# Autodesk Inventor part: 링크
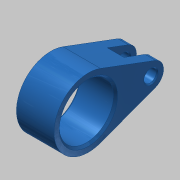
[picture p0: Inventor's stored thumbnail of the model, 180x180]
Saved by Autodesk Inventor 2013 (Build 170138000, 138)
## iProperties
Created: 2016-08
Part Number: 링크
Material: 강철, 탄소
Document SubType Name: Modeling
Designer: mduedu
Density: 7.87 g/cm^3
Mass: 80.4018 g
Surface Area: 54.1946 cm^2
Volume: 10.2162 cm^3
Author: mduedu
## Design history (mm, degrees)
sketch "스케치1"
  geometry: L1 (32.1, 5.62)-(5.775, 15.456); L2 (32.1, -5.62)-(5.775, -15.456); C1 r 13 at (0, 0); C2 r 3 at (30, 0); A1 r 16.5 centre (0, 0) between (5.775, 15.456) and (5.775, -15.456); A2 r 6 centre (30, 0) between (32.1, 5.62) and (32.1, -5.62); 1 further point
  constraints: 4 centre point, 4 end point, 4 point on circle, 4 tangent, 3 coincident, 1 horizontal alignment
  dimensions: "d0" = 33 diameter of A1; "d2" = 12 diameter of A2; "d3" = 30 distance of A2.centre point (0, 0); "d4" = 26 diameter of C1; "d5" = 6 diameter of C2
extrude "돌출1" new body sketch "스케치1" stored distance "d6" = 18; taper "d7" = 0 deg
sketch "스케치2"
  geometry: L1 (-9, 36)-(9, 36) reference; L2 (0, 0)-(0, 36); L3 (-4, 36)-(4, 36); L4 (4, 36)-(4, 22); L5 (4, 22)-(-4, 22); L6 (-4, 22)-(-4, 36)
  constraints: 10 end point, 2 midpoint, 2 parallel, 1 horizontal, 1 perpendicular, 1 point on line
  dimensions: "d8" = 8 distance between parallel lines of L4 L6; "d10" = 14 distance of L3.end L4.end
extrude "돌출2" cut sketch "스케치2" stored distance "d11" = 20; taper "d12" = 0 deg
chamfer "모따기1" distance "d13" = 1; stored, may be unused: second distance "d14" = 2, angle "d15" = 45 deg
chamfer "모따기2" distance "d16" = 0.5; stored, may be unused: second distance "d17" = 2, angle "d18" = 45 deg
node "솔리드1"
